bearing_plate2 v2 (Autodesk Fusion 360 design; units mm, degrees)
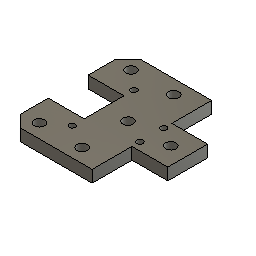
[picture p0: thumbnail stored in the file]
parameter "separation" = 43
parameter "hole_01" = 5.2
sketch "Sketch1" plane through (0, 0, 0) normal (0, 1, 0) x axis (1, 0, 0)
  line L1 (10, 25) -> (-50, 25)
  line L2 (-50, -35) -> (10, -35)
  line L3 (-50, 25) -> (-50, -35)
  line L4 (-20, -33) -> (-20, -35)
  line L5 (-20, 29) -> (-20, -33)
  line L6 (12, -5) -> (-50, -5)
  line L7 (30, 5) -> (10, 5)
  line L8 (30, -15) -> (30, 5)
  line L9 (10, -15) -> (30, -15)
  line L10 (10, 5) -> (10, 25)
  line L11 (10, -35) -> (10, -15)
  line L12 (-41, -7.6) -> (-42, -7.6)
  line L13 (-42, -2.4) -> (-41, -2.4)
  line L14 (-41, -5) -> (-42, -5)
  circle C1 centre (-41.5, -28) radius 2.6
  circle C2 centre (23, -5) radius 2.6
  circle C3 centre (-20, -28) radius 2.6
  circle C4 centre (1.5, -28) radius 2.6
  circle C5 centre (-20, -5) radius 2.6
  circle C6 centre (1.5, -5) radius 2.6
  circle C7 centre (-41.5, 18) radius 2.6
  circle C8 centre (-20, 18) radius 2.6
  circle C9 centre (1.5, 18) radius 2.6
  arc A1 centre (-41, -5) radius 2.6 clockwise from (-41, -2.4) to (-41, -7.6)
  arc A2 centre (-42, -5) radius 2.6 clockwise from (-42, -7.6) to (-42, -2.4)
  point P6 (-20, -35)
  point P9 (-50, -5)
  point P29 (-41, -5)
  point P30 (-41.5, -5)
  point P2 (-50, 25)
  point P5 (-50, -35)
  point P3 (10, 25)
  point P11 (-41.5, -28)
  point P13 (30, 5)
  point P14 (30, -15)
  point P15 (10, -15)
  horizontal L1
  vertical L10
  horizontal L2
  vertical L3
  midpoint L2 P6
  perpendicular L2 L4
  perpendicular L1 L5
  midpoint L3 P9
  horizontal L7
  vertical L8
  horizontal L9
  collinear L10 L11
  tangent L12 A1
  tangent A1 L13
  parallel L12 L13
  tangent L13 A2
  tangent L12 A2
  coincident L6 P29
  parallel L6 L14
  midpoint L14 P30
  dimension "d1" distance P2 P5 = 60
  dimension "d2" distance P2 P3 = 60
  dimension "d21" diameter C1 = 5.2 (= "hole_01")
  dimension "d22" distance L5 P11 = 21.5 (= "separation / 2")
  dimension "d35" distance P13 P14 = 20
  dimension "d36" distance P14 P15 = 20
  dimension "d38" diameter C2 = 5.2 (= "hole_01")
  dimension "d48" distance L6 P11 = 23
  dimension "d46" R-Pattern2-uDistance = 21.5 (= "separation / 2")
  dimension "d47" R-Pattern2-vDistance = 23
extrude "Extrude1" new body sketch "Sketch1" profile of L1 L11 L2 L3 C1 L7 L8 L9 C2 C3 C4 C5 C6 C7 C8 C9 L12 A1 L13 A2 along normal blind 6
chamfer "Chamfer1" distance 6
fillet "Fillet1" radius 3
fillet "Fillet2" radius 3
sketch "Sketch6" plane through (0, 6, 0) normal (0, 1, 0) x axis (-1, 0, 0)
  line L1 (-13, -5) -> (-27, -5)
  line L2 (-10, -19) -> (-10, -8)
  line L3 (-4, -25) -> (-10, -19)
  line L4 (44, -25) -> (-4, -25)
  line L5 (50, -19) -> (44, -25)
  line L6 (50, 29) -> (50, -19)
  line L7 (44, 35) -> (50, 29)
  line L8 (-4, 35) -> (44, 35)
  line L9 (-10, 29) -> (-4, 35)
  line L10 (-10, 18) -> (-10, 29)
  line L11 (-27, 15) -> (-13, 15)
  line L12 (-30, -2) -> (-30, 12)
  line L13 (41, 2.4) -> (42, 2.4)
  line L14 (42, 7.6) -> (41, 7.6)
  arc A1 centre (-27, -2) radius 3 clockwise from (-27, -5) to (-30, -2)
  arc A2 centre (-13, -8) radius 3 clockwise from (-13, -5) to (-10, -8)
  arc A3 centre (-13, 18) radius 3 clockwise from (-10, 18) to (-13, 15)
  arc A4 centre (-27, 12) radius 3 clockwise from (-30, 12) to (-27, 15)
  circle C1 centre (41.5, 28) radius 2.6
  circle C2 centre (-23, 5) radius 2.6
  circle C3 centre (20, 28) radius 2.6
  circle C4 centre (-1.5, 28) radius 2.6
  circle C5 centre (20, 5) radius 2.6
  circle C6 centre (-1.5, 5) radius 2.6
  circle C7 centre (41.5, -18) radius 2.6
  circle C8 centre (20, -18) radius 2.6
  circle C9 centre (-1.5, -18) radius 2.6
  arc A5 centre (42, 5) radius 2.6 clockwise from (42, 7.6) to (42, 2.4)
  arc A6 centre (41, 5) radius 2.6 clockwise from (41, 2.4) to (41, 7.6)
sketch "Sketch7" plane through (0, 6, 0) normal (0, 1, 0) x axis (-1, 0, 0)
  line L1 (-13, -5) -> (-27, -5)
  line L2 (-10, -19) -> (-10, -8)
  line L3 (-4, -25) -> (-10, -19)
  line L4 (44, -25) -> (-4, -25)
  line L5 (50, -19) -> (44, -25)
  line L6 (50, 29) -> (50, -19)
  line L7 (44, 35) -> (50, 29)
  line L8 (-4, 35) -> (44, 35)
  line L9 (-10, 29) -> (-4, 35)
  line L10 (-10, 18) -> (-10, 29)
  line L11 (-27, 15) -> (-13, 15)
  line L12 (-30, -2) -> (-30, 12)
  line L13 (41, 2.4) -> (42, 2.4)
  line L14 (42, 7.6) -> (41, 7.6)
  line L15 (8, -5) -> (8, -25)
  line L16 (-10, -5) -> (8, -5)
  line L17 (-10, 15) -> (-10, -5)
  line L18 (8, 15) -> (-10, 15)
  line L19 (8, 35) -> (8, 15)
  line L20 (-10, -5) -> (-10, -25)
  line L21 (32, -5) -> (50, -5)
  line L22 (32, 15) -> (32, -5)
  line L23 (50, 15) -> (32, 15)
  arc A1 centre (-27, -2) radius 3 clockwise from (-27, -5) to (-30, -2)
  arc A2 centre (-13, -8) radius 3 clockwise from (-13, -5) to (-10, -8)
  arc A3 centre (-13, 18) radius 3 clockwise from (-10, 18) to (-13, 15)
  arc A4 centre (-27, 12) radius 3 clockwise from (-30, 12) to (-27, 15)
  circle C1 centre (41.5, 28) radius 2.6
  circle C2 centre (-23, 5) radius 2.6
  circle C3 centre (20, 28) radius 2.6
  circle C4 centre (-1.5, 28) radius 2.6
  circle C5 centre (20, 5) radius 2.6
  circle C6 centre (-1.5, 5) radius 2.6
  circle C7 centre (41.5, -18) radius 2.6
  circle C8 centre (20, -18) radius 2.6
  circle C9 centre (-1.5, -18) radius 2.6
  arc A5 centre (42, 5) radius 2.6 clockwise from (42, 7.6) to (42, 2.4)
  arc A6 centre (41, 5) radius 2.6 clockwise from (41, 2.4) to (41, 7.6)
  point P37 (8, -25)
  point P42 (8, 35)
  point P43 (-10, 5)
  point P44 (-1.5, 5)
  point P39 (-10, -5)
  point P38 (8, -5)
  point P41 (8, 15)
  point P47 (50, -5)
  point P50 (50, 15)
  point P51 (32, 5)
  point P48 (32, -5)
  point P40 (-10, 15)
  coincident L4 P37
  perpendicular L4 L15
  perpendicular L15 L16
  perpendicular L16 L17
  perpendicular L17 L18
  coincident L8 P42
  perpendicular L8 L19
  midpoint L17 P43
  horizontal P43 P44
  coincident P39 L20
  vertical P38 P41
  coincident L6 P47
  perpendicular L6 L21
  perpendicular L21 L22
  coincident L6 P50
  perpendicular L6 L23
  midpoint L22 P51
  horizontal P43 P51
  horizontal P39 P48
  dimension "d49" distance P39 P40 = 20
  dimension "d50" distance P37 L20 = 18
  dimension "d51" distance P47 P48 = 18
extrude "Extrude2" cut sketch "Sketch7" profile of A1 L1 A2 L2 L3 L4 L6 L8 L9 L10 A3 L11 A4 L12 C2 C4 C9 A5 L13 A6 L14 L15 L16 L17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 against normal blind 21
sketch "Sketch8" plane through (0, 6, 0) normal (0, 1, 0) x axis (-1, 0, 0)
  line L1 (32, 15) -> (32, -5)
  line L2 (50, 15) -> (32, 15)
  line L3 (50, 29) -> (50, 15)
  line L4 (44, 35) -> (50, 29)
  line L5 (8, 35) -> (44, 35)
  line L6 (8, 15) -> (8, 35)
  line L7 (-10, 15) -> (8, 15)
  line L8 (-10, -5) -> (-10, 15)
  line L9 (8, -5) -> (-10, -5)
  line L10 (8, -25) -> (8, -5)
  line L11 (44, -25) -> (8, -25)
  line L12 (50, -19) -> (44, -25)
  line L13 (50, -5) -> (50, -19)
  line L14 (32, -5) -> (50, -5)
  line L15 (8, -5) -> (-0.5, -5)
  line L16 (-2.5, 15) -> (-10, 15)
  line L17 (40.5, -5) -> (32, -5)
  line L18 (50, 15) -> (42.5, 15)
  circle C1 centre (20, -18) radius 2.6
  circle C2 centre (41.5, -18) radius 2.6
  circle C3 centre (-1.5, 5) radius 2.6
  circle C4 centre (20, 5) radius 2.6
  circle C5 centre (20, 28) radius 2.6
  circle C6 centre (41.5, 28) radius 2.6
  point P19 (8, -5)
  point P27 (8, -5)
  point P16 (-10, 15)
  point P28 (-10, 15)
  point P25 (32, -5)
  point P30 (32, -5)
  point P10 (50, 15)
  point P33 (50, 15)
  coincident P19 P27
  coincident P16 P28
  coincident P25 P30
  coincident P10 P33
sketch "Sketch9" plane through (0, 6, 0) normal (0, 1, 0) x axis (-1, 0, 0)
  line L1 (8, 15) -> (8, 35)
  line L2 (-10, 15) -> (8, 15)
  line L3 (-10, -5) -> (-10, 15)
  line L4 (8, -5) -> (-10, -5)
  line L5 (8, -25) -> (8, -5)
  line L6 (44, -25) -> (8, -25)
  line L7 (50, -19) -> (44, -25)
  line L8 (50, -5) -> (50, -19)
  line L9 (32, -5) -> (50, -5)
  line L10 (32, 15) -> (32, -5)
  line L11 (50, 15) -> (32, 15)
  line L12 (50, 29) -> (50, 15)
  line L13 (44, 35) -> (50, 29)
  line L14 (8, 35) -> (44, 35)
  line L15 (20, -10) -> (32, -10)
  line L16 (8, -10) -> (20, -10)
  circle C1 centre (-1.5, 5) radius 2.6
  circle C2 centre (20, 5) radius 2.6
  circle C3 centre (41.5, -18) radius 2.6
  circle C4 centre (20, -18) radius 2.6
  circle C5 centre (20, 28) radius 2.6
  circle C6 centre (41.5, 28) radius 2.6
  circle C7 centre (32, -10) radius 1.5
  circle C8 centre (8, -1) radius 1.5
  circle C9 centre (8, 11) radius 1.5
  circle C10 centre (32, 21) radius 1.5
  point P22 (32, -10)
  point P24 (32, -10)
  point P3 (20, 5)
  point P25 (20, -10)
  point P23 (8, -1)
  point P26 (8, -10)
  point P27 (8, 11)
  point P28 (32, 21)
  coincident P22 P24
  horizontal L15
  vertical P3 P25
  parallel L15 L16
  equal L15 L16
  vertical P23 P26
  vertical P23 P27
  vertical P22 P28
  dimension "d56" diameter C8 = 3
  dimension "d59" diameter C7 = 3
  dimension "d60" distance P3 P22 = 15
  dimension "d62" distance P24 P25 = 12
  dimension "d63" distance P3 P23 = 6
  dimension "d64" diameter C10 = 3
  dimension "d65" diameter C9 = 3
  dimension "d66" distance P3 P27 = 6
  dimension "d67" distance P3 P28 = 16
extrude "Extrude4" cut sketch "Sketch9" profile of C7 C8 C9 C10 against normal blind 12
